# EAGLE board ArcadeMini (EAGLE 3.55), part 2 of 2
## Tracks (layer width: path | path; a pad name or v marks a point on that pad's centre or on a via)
CF_A0  (via drill 0.41 pad 0.81)
  Top 0.254: v79.12,42.81 78.7,42.39 69.79,42.39 67.6,42.39 62.09,47.89 v56.06,47.89 | 35.73,14.24 v39.87,14.24 | v88.45,49.16 99.56,49.16 101.47,47.26 101.47,35.83 103.05,34.24 104.07,34.24 | 44.95,21.23 44.95,22.49 45.59,23.13 v56.06,23.13 | 44.95,21.23 44.95,21.17 | v44.95,19.32 44.95,21.23
  Bottom 0.254: v79.12,42.81 79.88,42.81 81.46,44.4 82.1,44.4 86.86,49.16 v88.45,49.16 | 56.06,48.21 v56.06,47.89 v56.06,23.13 | v39.87,14.24 v44.95,19.32
CF_A1  (via drill 0.41 pad 0.81)
  Top 0.254: v79.12,41.55 78.78,41.89 69.79,41.89 67.15,41.89 62.41,46.62 55.43,46.62 54.48,47.58 54.48,53.61 53.2,54.88 52.24,54.88 | v88.45,47.89 89.08,48.53 99.24,48.53 100.83,46.94 100.83,32.97 101.47,32.34 102.42,32.34 103.05,32.97 104.07,32.97
  Bottom 0.254: v79.12,41.55 79.56,41.55 81.78,43.77 82.42,43.77 86.54,47.89 v88.45,47.89
CF_A2  (via drill 0.41 pad 0.81)
  Top 0.254: v79.12,40.27 78.01,41.39 69.79,41.39 66.7,41.39 62.09,45.99 55.11,45.99 53.83,47.27 53.83,51.06 53.84,51.07 52.57,52.34 52.24,52.34 | v88.45,46.62 88.77,46.62 90.04,47.89 98.93,47.89 100.2,46.62 100.2,32.34 100.83,31.7 104.07,31.7
  Bottom 0.254: v79.12,40.27 79.24,40.27 82.1,43.13 82.73,43.13 86.23,46.62 v88.45,46.62
CF_CD1/  (via drill 0.41 pad 0.81)
  Top 0.254: 69.79,40.89 72.8,40.89 v73.41,40.27 | v94.68,13.92 95.12,14.24 97.34,14.24 99.24,12.34 R16. 99.26,10.75 104.07,10.75
  Bottom 0.254: v73.41,40.27 73.09,39.96 73.09,35.83 74.68,34.24 74.8,27.89 72.89,25.99 72.89,22.81 73.84,21.86 73.84,20.91 76.7,18.05 90.56,18.05 v94.68,13.92
CF_CE/  (via drill 0.41 pad 0.81)
  Top 0.254: v103.89,50.75 103.37,50.75 102.42,51.7 88.02,51.7 86.86,50.55 86.86,42.81 86.44,42.39 83.39,42.39 | 104.01,17.73 104.07,17.73 v107.07,17.73
  Bottom 0.254: v107.07,17.73 107.07,50.12 106.43,50.75 v103.89,50.75
CF_D0  (via drill 0.41 pad 0.81)
  Top 0.254: v93.73,12.65 93.73,11.37 | v73.09,43.45 73.09,44.4 72.34,45.16 72.34,46.44 | 46.22,21.17 46.22,19.95 50.66,15.51 70.35,15.51 73.53,18.69 v73.53,19.95 | 108.13,35.51 v108.02,35.51 104.07,35.51 103.05,35.51 102.1,36.46 102.1,43.13 107.18,48.21 107.18,51.07 102.1,56.15 102.1,60.59 100.83,61.86 100.83,63.08 100.83,63.13
  Bottom 0.254: v73.09,43.45 72.46,43.13 72.46,35.51 74.05,33.92 74.05,28.09 72.26,26.3 72.26,22.49 73.21,21.54 73.21,20.27 v73.53,19.95 76.07,17.41 88.97,17.41 v93.73,12.65 95.32,11.07 104.84,11.07 108.97,15.19 108.97,34.56 v108.02,35.51
CF_D1  (via drill 0.41 pad 0.81)
  Top 0.254: v91.19,12.65 91.19,11.37 | IC2. 71.84,46.62 70.23,46.62 v69.6,47.26 | 47.49,21.17 47.49,19.95 51.3,16.14 68.76,16.14 v71.94,19.32 | 108.13,36.78 v108.02,36.78 104.07,36.78 103.05,36.78 102.73,37.1 102.73,42.81 107.82,47.89 107.82,51.39 102.73,56.47 102.73,61.23 102.1,61.86 102.1,63.08 102.1,63.13
  Bottom 0.254: v69.6,47.26 71.82,45.04 71.82,34.88 73.41,33.29 73.41,28.41 71.62,26.62 71.62,22.18 72.57,21.23 72.57,19.32 | v108.02,36.78 108.65,36.78 109.61,35.83 109.61,14.56 105.48,10.43 93.73,10.43 v91.19,12.65 87.06,16.78 75.43,16.78 72.57,19.32 | v71.94,19.32 72.57,19.32
CF_D2  (via drill 0.41 pad 0.81)
  Top 0.254: v88.65,12.65 88.65,11.37 | 69.79,44.39 70.54,44.39 70.87,44.72 70.87,45.35 70.23,45.99 v69.28,45.99 | 48.76,21.17 48.76,19.95 51.94,16.78 66.86,16.78 70.67,20.59 v71.62,20.59 | 108.13,38.05 v108.02,38.05 104.07,38.05
  Bottom 0.254: v69.28,45.99 71.19,44.09 71.19,34.24 72.78,32.66 72.78,28.73 70.98,26.94 70.98,24.08 | v108.02,38.05 109.29,38.05 110.24,37.1 110.24,13.92 106.11,9.79 91.51,9.79 v88.65,12.65 85.16,16.14 73.53,16.14 70.98,18.69 70.98,20.59 | 70.98,20.59 70.98,24.08 | 70.98,24.08 70.98,24.4 | v71.62,20.59 70.98,20.59
CF_D3  (via drill 0.41 pad 0.81)
  Top 0.254: 86.11,11.37 v86.11,12.65 86.11,13.29 87.7,14.88 98.49,14.88 101.98,11.38 104.07,11.38 | 69.79,43.89 68.84,43.89 68.33,44.4 v68.33,45.04 | 50.03,21.17 50.03,19.95 52.57,17.41 66.22,17.41 v69.4,20.59
  Bottom 0.254: v68.33,45.04 69.28,45.04 70.55,43.77 70.55,33.61 72.26,31.91 72.26,29.48 70.35,27.58 70.35,24.08 | v86.11,12.65 83.25,15.51 73.21,15.51 70.35,18.37 70.35,20.59 | 70.35,20.59 70.35,24.08 | 70.35,24.08 70.35,24.4 | v69.4,20.59 70.35,20.59
CF_D4  (via drill 0.41 pad 0.81)
  Top 0.254: 83.57,11.37 v83.57,12.65 83.57,13.29 85.79,15.51 99.13,15.51 101.98,12.65 104.07,12.65 | 72.34,32.84 72.34,31.58 72.14,31.38 v71.19,31.38 | 51.3,21.17 51.3,19.95 53.2,18.05 64.64,18.05 68.45,21.86 v69.4,21.86
  Bottom 0.254: v83.57,12.65 81.35,14.88 73.84,14.88 | 73.84,14.88 73.21,14.88 | v71.19,31.38 70.35,30.55 70.35,28.53 68.45,26.62 68.45,21.86 | 68.45,21.86 68.45,19.32 72.89,14.88 73.84,14.88 | v69.4,21.86 68.45,21.86
CF_D5  (via drill 0.41 pad 0.81)
  Top 0.254: 81.03,11.37 v81.03,12.65 81.03,13.29 83.89,16.14 99.76,16.14 101.98,13.92 104.07,13.92 | 71.84,32.84 71.84,32.66 v70.23,32.66 | 52.57,21.17 52.57,19.95 53.84,18.69 63.68,18.69 v66.86,21.86
  Bottom 0.254: v81.03,12.65 79.44,14.24 72.57,14.24 67.81,19 67.81,21.86 | 67.81,21.86 67.81,27.26 69.72,29.16 69.72,32.13 v70.23,32.66 | v66.86,21.86 67.81,21.86
CF_D6  (via drill 0.41 pad 0.81)
  Top 0.254: 78.49,11.37 v78.49,12.65 78.49,13.29 81.98,16.78 100.4,16.78 101.98,15.19 104.07,15.19 | 69.79,34.89 69.6,34.89 v69.6,33.92 | IC10. 53.84,19.95 54.48,19.32 62.09,19.32 65.91,23.13 v66.86,23.13
  Bottom 0.254: v78.49,12.65 78.17,12.65 77.22,13.61 72.26,13.61 65.91,19.95 65.91,23.13 | v69.6,33.92 69.08,33.41 69.08,29.8 65.91,26.62 65.91,23.13 | v66.86,23.13 65.91,23.13
CF_D7  (via drill 0.41 pad 0.81)
  Top 0.254: 75.95,11.37 v75.95,12.65 75.95,13.29 80.08,17.41 101.03,17.41 101.98,16.46 104.07,16.46 | v68.33,34.56 68.33,34.88 68.84,35.39 69.79,35.39 | 53.84,30.19 53.92,30.12 63.37,30.12 v65.27,28.21
  Bottom 0.254: v68.33,34.56 68.33,31.27 v65.27,28.21 65.27,19.64 71.94,12.97 75.63,12.97 v75.95,12.65
CF_OE/  (via drill 0.41 pad 0.81)
  Top 0.254: v106.11,49.48 106.11,51.07 103.89,53.29 87.06,53.29 85.59,51.82 85.59,44.09 84.9,43.39 83.39,43.39 | v106.55,16.14 107.18,16.14 107.82,15.51 v107.82,9.79 | v69.72,11.07 66.54,14.24 43.36,14.24 38.6,19 38.6,21.17 | 104.01,20.27 104.07,20.27 v106.23,20.27
  Bottom 0.254: v106.11,49.48 106.43,49.16 106.43,20.59 v106.23,20.27 106.23,16.46 v106.55,16.14 | v107.82,9.79 107.82,8.21 106.86,7.25 105.28,7.25 104.64,7.89 72.89,7.89 v69.72,11.07
CF_RDY  (via drill 0.41 pad 0.81)
  Top 0.254: v75.32,22.81 72.78,22.81 70.87,24.72 68.76,24.72 67.81,25.67 v64,25.67 | 69.79,39.89 66.29,39.89 61.46,44.72 57.33,44.72 56.06,43.45 56.06,38.37 61.14,33.29 v64,33.29 | v95.12,24.08 96.39,24.08 | 96.39,24.08 100.83,24.08 101.47,24.72 104.07,24.72 | 96.39,24.08 R15.
  Bottom 0.254: v64,25.67 v64,33.29 | v75.32,22.81 76.59,24.08 v95.12,24.08
CF_RST/  (via drill 0.41 pad 0.81)
  Top 0.254: v103.26,48.53 103.26,49.28 101.78,50.75 88.45,50.75 87.5,49.8 87.5,42.5 86.89,41.89 83.39,41.89 | 96.39,30.75 v102.1,30.75 103.05,29.8 104.07,29.8
  Bottom 0.254: v103.26,48.53 103.89,48.53 105.16,47.26 105.16,33.81 v102.1,30.75
CF_UCS/  (via drill 0.41 pad 0.81)
  Top 0.254: v74.8,24.08 72.57,24.08 71.3,25.35 69.08,25.35 67.49,26.94 62.09,26.94 59.55,24.4 39.23,24.4 37.33,22.49 37.33,21.17 | 83.39,41.39 87.34,41.39 88.13,42.18 88.13,44.72 89.4,45.99 v98.93,45.99
  Bottom 0.254: v74.8,24.08 75.75,25.03 94.48,25.03 99.56,30.12 99.56,45.35 v98.93,45.99
CF_URST/  (via drill 0.41 pad 0.81)
  Top 0.254: v74.8,25.35 72.89,25.35 72.26,25.99 70.03,25.99 64.95,31.07 58.6,31.07 56.38,33.29 55.24,33.29 | 52.57,30.19 52.57,31.38 54.48,33.29 55.24,33.29 | 83.39,40.89 87.79,40.89 88.77,41.86 88.77,44.4 89.72,45.35 97.97,45.35 v98.61,44.72 | 55.24,33.29 55.23,33.3
  Bottom 0.254: v74.8,25.35 75.11,25.67 94.16,25.67 98.61,30.12 v98.61,44.72
CF_WE/  (via drill 0.41 pad 0.81)
  Top 0.254: v104.21,49.48 104.53,49.48 105.16,50.12 105.16,51.07 103.57,52.66 87.7,52.66 86.23,51.18 86.23,49.8 | 83.39,42.89 85.67,42.89 86.23,43.45 86.23,49.8 | 86.23,49.8 86.23,50.43 | v106.55,8.53 v106.55,14.88 | v70.98,11.07 67.18,14.88 43.68,14.88 39.87,18.69 39.87,21.17 | v101.78,23.45 104.07,23.45
  Bottom 0.254: v104.21,49.48 104.53,49.48 105.8,48.21 105.8,24.08 105.16,23.45 103.37,23.45 | v106.55,14.88 105.91,14.88 103.37,17.41 103.37,23.45 | v70.98,11.07 73.53,8.53 v106.55,8.53 | 103.37,23.45 v101.78,23.45
COL0
  Top 0.254: 69.79,42.89 68.05,42.89 66.54,44.4 66.54,46.62 55.74,57.42 48.12,57.42 43.68,61.86 43.68,63.08 43.68,63.13
COL1
  Top 0.254: 69.79,43.39 68.51,43.39 67.18,44.72 67.18,47.26 56.38,58.05 48.76,58.05 44.95,61.86 44.95,63.08 44.95,63.13
COL2
  Top 0.254: 72.84,46.44 72.84,47.63 66.22,54.24 61.46,54.24 57.02,58.69 49.39,58.69 46.22,61.86 46.22,63.08 46.22,63.13
COL3
  Top 0.254: 73.34,46.44 73.34,48.09 66.54,54.88 62.09,54.88 57.65,59.32 50.03,59.32 47.49,61.86 47.49,63.08 47.49,63.13
COL4
  Top 0.254: 73.84,46.44 73.84,48.54 66.86,55.52 62.73,55.52 58.28,59.96 50.66,59.96 48.76,61.86 48.76,63.08 48.76,63.13
COL5
  Top 0.254: 74.34,46.44 74.34,48.99 67.18,56.15 63.37,56.15 58.92,60.59 51.3,60.59 50.03,61.86 50.03,63.08 50.03,63.13
COL6
  Top 0.254: 74.84,46.44 74.84,49.44 67.49,56.78 64,56.78 59.55,61.23 51.94,61.23 51.3,61.86 51.3,63.08 51.3,63.13
COL7
  Top 0.254: 75.34,46.44 75.34,49.89 67.81,57.42 64.64,57.42 60.19,61.86 60.19,63.08 60.19,63.13
COL8
  Top 0.254: 75.84,46.44 75.84,50.35 68.13,58.05 65.27,58.05 61.46,61.86 61.46,63.08 61.46,63.13
COL9
  Top 0.254: 77.34,46.44 77.34,56.47 75.11,58.69 65.91,58.69 62.73,61.86 62.73,63.08 62.73,63.13
COL10
  Top 0.254: 77.84,46.44 77.84,56.92 75.43,59.32 66.54,59.32 64,61.86 64,63.08 64,63.13
COL11
  Top 0.254: 78.34,46.44 78.34,57.37 75.75,59.96 67.18,59.96 65.27,61.86 65.27,63.08 65.27,63.13
COL12
  Top 0.254: 78.84,46.44 78.84,57.82 76.07,60.59 67.81,60.59 66.54,61.86 66.54,63.08 66.54,63.13
COL13
  Top 0.254: 79.34,46.44 79.34,58.28 76.38,61.23 68.45,61.23 67.81,61.86 67.81,63.08 67.81,63.13
COL14
  Top 0.254: 79.84,46.44 79.84,58.73 76.7,61.86 76.7,63.08 76.7,63.13
COL15
  Top 0.254: 80.34,46.44 80.34,59.5 77.97,61.86 77.97,63.08 77.97,63.13
COL16  (via drill 0.41 pad 0.81)
  Top 0.254: 79.34,32.84 79.34,31.81 v80.4,30.75 | 79.24,63.08 79.24,61.86 86.86,54.24 v96.39,54.24
  Bottom 0.254: v80.4,30.75 82.94,28.21 91.19,28.21 95.64,32.66 95.64,53.49 v96.39,54.24
COL17  (via drill 0.41 pad 0.81)
  Top 0.254: 78.84,32.84 78.84,31.04 v80.4,29.48 | 80.51,63.08 80.51,61.86 86.86,55.52 97.02,55.52 v97.66,54.88
  Bottom 0.254: v80.4,29.48 82.3,27.58 91.83,27.58 96.27,32.02 96.27,52.23 97.66,53.61 v97.66,54.88
COL18  (via drill 0.41 pad 0.81)
  Top 0.254: 81.78,63.08 81.78,61.86 86.86,56.78 93.21,56.78 v94.48,58.05 | 83.39,35.89 84.9,35.89 86.54,34.24 86.54,32.02 v87.5,31.07
  Bottom 0.254: v87.5,31.07 90.04,31.07 93.73,34.88 93.73,56.78 94.48,57.53 v94.48,58.05
COL19  (via drill 0.41 pad 0.81)
  Top 0.254: 83.05,63.08 83.05,61.86 86.86,58.05 93.21,58.05 v94.48,59.32 | 83.39,36.39 85.35,36.39 87.18,34.56 87.18,32.97 v87.81,32.34
  Bottom 0.254: v94.48,59.32 94.48,59.44 93.1,58.05 93.1,35.51 89.92,32.34 v87.81,32.34
COL20  (via drill 0.41 pad 0.81)
  Top 0.254: 84.32,63.08 84.32,61.86 86.86,59.32 v93.21,59.32 | 83.39,36.89 85.8,36.89 88.13,34.56 v88.13,33.61
  Bottom 0.254: v93.21,59.32 93.21,59.44 92.46,58.69 92.46,36.03 90.04,33.61 v88.13,33.61
COL21  (via drill 0.41 pad 0.81)
  Top 0.254: 83.39,37.39 86.46,37.39 v87.7,36.15 | v93.21,61.23 93.21,63.08
  Bottom 0.254: v87.7,36.15 90.56,36.15 91.83,37.42 91.83,59.96 v93.21,61.23
COL22  (via drill 0.41 pad 0.81)
  Top 0.254: 79.84,32.84 79.84,33.85 v79.12,34.56 | 94.48,63.08 94.48,60.91 95.75,59.64 95.75,57.42 v96.39,56.78
  Bottom 0.254: v79.12,34.56 81.46,32.66 81.46,30.63 83.25,28.84 90.56,28.84 95,33.29 95,55.4 v96.39,56.78
COL23  (via drill 0.41 pad 0.81)
  Top 0.254: 80.34,32.84 80.34,34.94 v80.08,35.2 | 95.75,63.13 95.75,63.08 v95.75,61.23
  Bottom 0.254: v80.08,35.2 80.08,34.88 82.1,32.97 82.1,31.27 83.89,29.48 89.92,29.48 94.37,33.92 94.37,56.27 95.75,57.74 v95.75,61.23
COL24  (via drill 0.41 pad 0.81)
  Top 0.254: 78.34,32.84 78.34,30.27 v79.12,29.48 | 97.02,63.08 v97.02,58.69 R17.
  Bottom 0.254: v79.12,29.48 81.67,26.94 92.46,26.94 96.91,31.38 96.91,51.59 98.93,53.61 98.93,56.78 v97.02,58.69
COL25  (via drill 0.41 pad 0.81)
  Top 0.254: 77.84,29.5 77.84,32.84 | v98.29,61.23 98.29,63.08
  Top 0.305: v79.76,26.94 79.76,27.37 77.84,29.3 77.84,29.5
  Bottom 0.254: v79.76,26.94 80.4,26.3 93.1,26.3 97.54,30.75 97.54,50.95 99.56,52.98 99.56,57.42 98.29,58.69 v98.29,61.23
GND  (via drill 0.41 pad 0.81)
  Top 0.254: 71.44,39.39 69.79,39.39 65.84,39.39 64.95,40.27 64.32,40.27 64,40.59 | 73.09,35.83 74.34,34.59 74.34,32.84 74.34,31.53 74.69,31.17 C4. | 77.22,44.72 76.84,45.1 76.84,46.44 76.84,52.52 76.07,53.29 | 105.28,9.16 105.28,9.79 104.96,10.11 104.07,10.11 | 76.84,32.84 76.84,31.52 76.38,31.07 | 83.4,39.89 83.39,39.89 | v80.51,39.89 83.4,39.89 | 101.78,22.18 102.42,22.81 104.07,22.81 105.91,22.81 | C9. 96.72,29.17 96.4,28.86 | 83.4,39.89 88.38,39.89 88.77,40.27 | 106.23,41.23 104.07,41.23 | 104.01,30.43 104.07,30.43 105.8,30.43 | 105.91,29.16 104.07,29.16 | 104.07,27.26 104.07,26.62 104.01,26.62 | 105.91,27.26 104.07,27.26 | 104.07,27.26 104.07,27.89 102.42,27.89 | 104.01,19 104.07,19 105.8,19 | 105.91,24.08 104.07,24.08 | 105.91,21.54 104.07,21.54 | R2. 55.23,35.2 52.27,35.2
  Top 0.406: 73.09,39.32 71.44,39.39 | 73.09,39.32 73.09,35.83 | 77.22,44.72 78.81,44.72 80.51,43.02 v80.51,39.89 79.95,39.32 73.09,39.32
  Top 0.61: 18.91,84.09 22.72,84.09 | 22.72,56.15 22.78,56.15 | 18.91,70.12 22.72,70.12 | 22.72,70.12 22.78,70.12 | 22.78,68.85 22.78,70.07 22.72,70.12 | 22.72,56.15 22.72,54.88 22.78,54.88 | 22.72,84.09 22.78,84.09 | 22.72,84.09 22.78,84.04 22.72,83.99 22.72,82.82 22.78,82.82 22.72,82.77 22.72,81.55 22.78,81.55 | 42.41,69.48 42.41,63.08 | 52.57,63.08 53.79,63.08 53.84,63.13 53.84,63.08 53.89,63.13 53.84,63.19 53.84,69.48 | 58.92,69.48 58.92,63.08 | 69.08,63.08 69.13,63.13 70.35,63.13 | 70.35,63.13 70.35,63.08 | 70.35,69.48 70.35,63.13 | 75.43,69.48 75.43,63.08 | 85.59,63.08 85.64,63.13 86.86,63.13 | 86.86,63.13 86.86,63.08 | 86.86,69.48 86.86,63.13 | 91.94,69.48 91.94,63.08 | 99.56,65.04 99.56,63.08 | 109.61,41.23 106.23,41.23 106.11,41.23 | 109.61,29.16 105.91,29.16 105.8,29.16 | 109.61,19 105.8,19 | 109.61,21.54 105.91,21.54 105.8,21.54 | 109.61,30.43 105.8,30.43 | 109.61,27.26 105.91,27.26 105.8,27.26 | 109.61,24.08 105.91,24.08 105.8,24.08 | 109.61,22.81 105.91,22.81 105.8,22.81 | 93.21,72.1 93.21,69.48 97.66,65.04 99.56,65.04 | 76.7,69.48 76.7,72.1 | 60.19,69.48 60.19,72.1 | 22.72,56.78 22.72,56.15 | 105.28,9.16 105.28,7.89 106.23,6.94 107.18,6.94 109.61,9.36 | 41.14,30.19 41.14,30.12 41.22,30.19 42.41,30.19 43.6,30.19 43.68,30.12 | 43.68,30.12 43.68,30.19 | 43.68,69.48 43.68,72.1 | C4. 76.28,31.17 76.38,31.07 77.02,30.43 77.02,28.84 78.61,27.26 78.61,25.67 80.51,25.67 81.78,26.94 81.78,31.38 82.73,32.34 v82.73,33.61 | C6. 75.43,54.87 75.43,53.93 76.07,53.29 | 86.54,26.95 84.96,28.54 v84.96,30.43 | 86.54,26.95 C7. | 86.54,26.95 86.54,25.35 88.77,23.13 88.77,21.34 | 88.77,21.34 88.65,21.23 | 88.77,21.34 88.77,21.23
  Top 0.61: 51.3,25.67 46.22,25.67 | 46.22,25.67 46.22,30.19 | 46.22,25.67 44.95,25.67 43.68,26.94 43.68,30.12 | 51.3,25.67 51.3,30.19 51.3,32.66 52.27,33.62 52.27,35.2 52.27,38.67 44.95,45.99 44.95,48.53 | 51.3,25.67 v54.48,25.67 57.34,25.67 C10. | 33.52,41.85 33.53,41.86 41.13,41.86 41.14,41.85 42.1,41.85 43.68,40.27 43.68,30.12 | 64,40.59 61.47,43.12 C5. | C8. 101.48,21.87 101.78,22.18 | C9. 101.14,29.17 102.42,27.89 | C17. 96.39,40.6 96.39,39.64 | C16. 96.39,38.68 96.39,39.64 | 96.39,39.64 97.34,39.64 98.61,40.91 98.61,42.81 97.34,44.09 90.99,44.09 89.72,42.81 89.72,41.23 88.77,40.27 | 99.56,65.04 102.73,65.04 103.37,64.41 103.37,63.08
  Top 1.27: 18.91,56.78 18.91,70.12 18.91,84.09 | 39.87,69.48 42.41,69.48 43.68,69.48 53.84,69.48 56.38,69.48 | 72.89,69.48 C13. | 56.38,69.48 58.92,69.48 60.19,69.48 70.35,69.48 72.89,69.48 | 89.4,69.48 C14. | 72.89,69.48 75.43,69.48 76.7,69.48 86.86,69.48 89.4,69.48 | 89.4,69.48 91.94,69.48 93.21,69.48 | 56.38,69.48 C12. | 39.87,69.48 37.96,67.58 37.96,59.32 35.42,56.78 22.72,56.78 18.91,56.78 | 39.87,69.48 C11. | 74.48,15.83 78.61,19.95 78.61,25.67 | 111.94,2.81 135.75,2.81 | 135.75,48.53 114.05,48.53 112.26,46.94 112.26,43.88 109.61,41.23 109.61,30.43 109.61,29.16 109.61,27.26 109.61,24.08 109.61,22.81 109.61,21.54 109.61,19 109.61,9.36 111.94,6.94 111.94,2.81 | 73.21,2.81 73.41,2.81 CON3. 73.41,14.76 74.48,15.83 | 73.21,2.81 111.94,2.81 | 74.48,15.83 74.16,15.51 | 18.3,39.61 18.36,39.61 | 4.3,20.59 C1. 8.12,30.75 11.3,30.75 13.84,33.29 13.84,35.14 18.3,39.61 | 4.3,20.59 C2. 4.32,14.24 4.32,12.96 11.93,5.35 15.74,5.35 | 4.3,20.59 4.63,20.59 | 18.3,39.61 18.33,39.64 18.33,39.37 | 18.33,39.37 18.28,39.32 | 18.91,56.78 18.91,39.96 18.33,39.37 | 15.74,5.35 28.44,5.35 | 15.74,5.35 R14. | 43.78,5.35 43.78,5.41 | 28.44,5.35 C3. | 28.44,5.35 43.78,5.35 | 43.78,5.35 51.3,5.35 | 51.3,5.35 56.22,5.35 CON6. 58.88,2.81 73.21,2.81 | 51.28,8.16 51.3,8.14 51.3,5.35
  Bottom 0.406: v80.51,39.89 82.73,37.67 v82.73,33.61
  Bottom 0.61: v82.73,33.61 82.73,32.02 84.32,30.43 v84.96,30.43
  Bottom 1.27: v54.48,25.67 54.48,21.23 55.43,20.27 57.65,20.27 73.21,5.35 CON3.
N$1
  Top 0.406: 83.57,5.35 R7.
N$2
  Top 0.406: 86.11,5.35 R6.
N$3  (via drill 0.41 pad 0.81)
  Top 0.254: 70.03,28.21 71.51,26.62 v75,26.62 | 70.03,28.21 69.72,28.21 65.91,32.02 61.46,32.02 55.11,38.37 55.11,43.45 57.02,45.35 61.78,45.35 66.74,40.39 69.79,40.39 | 70.03,28.21 R1.
  Bottom 0.254: 93.73,21.23 91.83,23.13 77.97,23.13 76.7,21.86 74.8,21.86 73.84,22.81 73.84,25.67 74.8,26.62 v75,26.62
N$4
  Top 0.406: 88.65,5.35 R5.
N$5
  Top 0.406: 91.19,5.35 R4.
N$6
  Top 0.406: 93.73,5.35 R3.
N$7
  Top 0.254: 92.58,37.42 Q1. | 83.39,38.89 91.1,38.89 92.58,37.42 | 96.4,36.79 93.2,36.79 92.58,37.42
N$8
  Top 0.254: 83.39,39.39 90.1,39.39 92.58,41.86 | 92.58,41.86 92.58,41.89 | 96.4,42.49 93.2,42.49 92.58,41.86
N$9  (via drill 0.41 pad 0.81)
  Top 0.254: 83.39,40.39 82.3,40.39 v81.78,40.91 | v84,32.34 82.73,31.07 82.73,22.06 CON2.
  Bottom 0.254: v81.78,40.91 83.69,39 83.69,32.66 v84,32.34
N$10
  Top 0.254: 83.39,37.89 87.34,37.89 89.08,36.15 89.08,31.07 88.13,30.12 86.86,30.12 85.59,31.38 84.32,31.38 83.37,30.43 83.37,23.97 86.11,21.23
N$11
  Top 0.406: 81.03,5.35 R8.
N$12
  Top 0.406: 78.49,5.35 R9.
N$13
  Top 0.406: 75.95,5.35 R10.
N$14
  Top 0.406: 6.85,52.34 5.58,53.61 3.67,53.61 3.04,52.98 3.04,48.53 5.58,45.99 8.44,45.99 13.76,45.99
N$15
  Top 0.406: 4.31,52.34 4.31,49.16 6.21,47.26 13.76,47.26
N$16
  Top 0.406: 6.85,54.88 8.12,53.61 8.12,50.43 10.03,48.53 13.76,48.53
N$17
  Top 0.406: 4.31,54.88 5.58,56.15 8.75,56.15 9.39,55.52 9.39,51.07 10.66,49.8 13.76,49.8
N$18
  Top 0.406: 6.85,57.42 9.39,57.42 10.66,56.15 10.66,51.7 11.3,51.07 13.76,51.07
N$19  (via drill 0.41 pad 0.81)
  Top 0.406: v11.93,52.34 13.76,52.34
  Bottom 0.406: v11.93,52.34 8.12,56.15 5.58,56.15 4.31,57.42
N$20
  Top 0.406: 6.85,59.96 8.12,58.69 10.66,58.69 11.93,57.42 11.93,54.24 12.57,53.61 13.76,53.61
N$21
  Top 0.406: 4.31,59.96 5.58,61.23 7.49,61.23 8.75,59.96 13.76,59.96
N$22
  Top 0.406: 6.85,62.5 8.12,62.5 9.39,61.23 13.76,61.23
N$23
  Top 0.406: 4.31,62.5 5.58,63.77 8.75,63.77 10.03,62.5 13.76,62.5
N$24
  Top 0.406: 6.85,65.04 9.39,65.04 10.66,63.77 13.76,63.77
N$25
  Top 0.406: 4.31,65.04 5.58,66.31 10.03,66.31 11.3,65.04 13.76,65.04
N$26
  Top 0.406: 6.85,67.58 10.66,67.58 11.93,66.31 13.76,66.31
N$27
  Top 0.406: 4.31,67.58 5.58,68.85 11.3,68.85 12.57,67.58 13.76,67.58
N$28
  Top 0.406: CON5. 9.39,80.28 13.76,80.28
N$29
  Top 0.406: 6.85,75.2 10.66,79.01 13.76,79.01
N$30
  Top 0.406: 4.31,72.66 5.58,73.93 7.49,73.93 11.3,77.74 13.76,77.74
N$31
  Top 0.406: 6.85,72.66 8.12,72.66 11.93,76.47 13.76,76.47
N$32
  Top 0.406: 4.31,70.12 5.58,71.39 8.75,71.39 12.57,75.2 13.76,75.2
N$33
  Top 0.406: 6.85,70.12 9.39,70.12 13.2,73.93 13.76,73.93
N$34
  Top 0.406: 57.65,80.28 57.65,79.01 56.38,77.74 47.49,77.74 44.95,75.2 44.95,72.1
N$35  (via drill 0.41 pad 0.81)
  Top 0.406: 46.22,72.1 v46.22,73.93
  Bottom 0.406: v46.22,73.93 48.76,76.47 55.11,76.47 56.38,77.74 56.38,81.55 57.65,82.82
N$36
  Top 0.406: 60.19,80.28 60.19,79.01 57.65,76.47 49.39,76.47 47.49,74.56 47.49,72.1
N$37  (via drill 0.41 pad 0.81)
  Top 0.406: 48.76,72.1 v48.76,73.93
  Bottom 0.406: v48.76,73.93 50.03,75.2 56.38,75.2 58.92,77.74 58.92,81.55 60.19,82.82
N$38
  Top 0.406: 62.73,80.28 62.73,79.01 58.92,75.2 50.66,75.2 50.03,74.56 50.03,72.1
N$39  (via drill 0.41 pad 0.81)
  Top 0.406: 51.3,72.1 v51.3,73.93
  Bottom 0.406: v51.3,73.93 57.65,73.93 61.46,77.74 61.46,81.55 62.73,82.82
N$40
  Top 0.406: 65.27,80.28 65.27,79.64 59.55,73.93 53.2,73.93 52.57,73.3 52.57,72.1
N$41  (via drill 0.41 pad 0.81)
  Top 0.406: 61.46,72.1 v61.46,73.93
  Bottom 0.406: v61.46,73.93 61.46,75.83 64,78.38 64,81.55 65.27,82.82
N$42
  Top 0.406: 67.81,80.28 67.81,79.64 62.73,74.56 62.73,72.1
N$43  (via drill 0.41 pad 0.81)
  Top 0.406: 64,72.1 v64,73.93
  Bottom 0.406: 67.81,82.82 66.54,81.55 66.54,77.74 64,75.2 v64,73.93
N$44
  Top 0.406: 70.35,80.28 70.35,79.64 65.27,74.56 65.27,72.1
N$45  (via drill 0.41 pad 0.81)
  Top 0.406: 66.54,72.1 v66.54,73.93
  Bottom 0.406: v66.54,73.93 66.54,74.56 69.08,77.11 69.08,81.55 70.35,82.82
N$46
  Top 0.406: 72.89,80.28 72.89,79.64 67.81,74.56 67.81,72.1
N$47
  Top 0.406: 72.89,82.82 74.16,81.55 74.16,79.01 69.08,73.93 69.08,72.1
N$48
  Top 0.406: CON4. 91.94,79.01 96.39,79.01 99.56,75.83 99.56,72.1
N$49
  Top 0.406: 88.13,80.28 90.67,77.74 95.75,77.74 98.29,75.2 98.29,72.1 98.29,72.02
N$50
  Top 0.406: 85.59,82.82 86.86,81.55 86.86,79.01 89.4,76.47 95.12,76.47 97.02,74.56 97.02,72.1 97.02,72.02
N$51
  Top 0.406: 85.59,80.28 85.59,78.38 88.77,75.2 94.48,75.2 95.75,73.93 95.75,72.1
N$52
  Top 0.406: 83.05,82.82 84.32,81.55 84.32,77.74 88.13,73.93 93.85,73.93 94.48,73.3 94.48,72.1
N$53
  Top 0.406: 83.05,80.28 83.05,77.74 85.59,73.93 85.59,72.1
N$54
  Top 0.406: 80.51,82.82 81.78,81.55 81.78,77.74 84.32,73.93 84.32,72.1
N$55
  Top 0.406: 80.51,80.28 80.51,77.74 83.05,73.93 83.05,72.1
N$56
  Top 0.406: 77.97,82.82 79.24,81.55 79.24,77.74 81.78,73.93 81.78,72.1
N$57
  Top 0.406: 77.97,80.28 77.97,77.74 80.51,73.93 80.51,72.1
N$58
  Top 0.406: 75.43,82.82 76.7,81.55 76.7,77.74 79.24,73.93 79.24,72.1
N$59
  Top 0.406: 75.43,80.28 75.43,77.74 77.97,73.93 77.97,72.1
N$60
  Top 0.254: 39.58,39.64 Q2. 39.87,35.54 39.87,30.19 39.87,30.12 | 39.58,39.64 38.27,39.64 | 39.58,39.64 39.55,39.61 40.8,39.61 41.14,39.96 C19.
N$61
  Top 0.254: 35.08,39.64 35.08,35.83 35.08,34.91 38.6,31.38 38.6,30.19 38.6,30.12 | 35.08,39.64 R11. | C18. 33.52,39.96 33.84,39.64 35.08,39.64
N$62
  Top 0.254: 46.22,35.5 46.22,35.51 49.06,35.51 C15.
  Top 0.61: 50.03,30.19 50.03,32.66 49.06,33.62 C15.
N$63
  Top 1.27: D2. 13.2,20.59 IC1. 28.44,20.59
  Top 6.452: 19.55,24.4 28.44,24.4 28.44,20.59 28.44,16.78 19.55,16.78
N$64  (via drill 0.41 pad 0.81)
  Top 0.254: v47.49,28.21 47.49,30.19
  Bottom 0.254: 48.76,10.14 48.76,10.11 | 48.78,10.16 48.76,10.14 | v47.49,28.21 48.76,28.21 49.39,27.58 49.39,26.62 48.76,25.99 48.76,10.14
N$65  (via drill 0.41 pad 0.81)
  Top 0.254: v48.12,26.94 48.76,27.58 48.76,30.19 48.76,31.38 46.52,33.62 R12.
  Bottom 0.254: v48.12,26.94 48.12,11.7 47.17,10.75 47.17,9.48 48.44,8.21 48.76,8.21 48.76,8.18 48.78,8.16
N$66
  Top 1.27: D4. 40.82,10.11 43.36,12.65 49.71,12.65 51.3,11.07 51.3,10.18 51.28,10.16
N$67
  Top 0.406: 95.43,20.91 96.07,21.54 96.07,19.95
N$68
  Top 0.406: 98.29,5.99 98.93,6.62 98.93,4.71
N$69
  Top 0.406: 55.11,80.28 55.74,80.91 55.74,79.01
N$70
  Top 0.406: 6.21,49.8 6.85,50.43 6.85,48.53
N$71
  Top 0.254: 44.62,52.34 44.95,52.34 46.22,51.07 46.22,47.89 47.49,46.62 49.39,46.62 50.03,47.26 50.03,48.53 50.03,52.01 R19.
N$72
  Top 0.254: 47.49,54.88 R18. | 47.49,54.88 44.62,54.88 | CON7. 47.49,54.88
N$73
  Top 0.406: 34.79,49.8 35.42,50.43 35.42,48.53
N$74  (via drill 0.41 pad 0.81)
  Top 0.254: 102.1,72.1 102.1,70.75 99.56,68.22 v96.39,68.22 | v39.87,67.26 39.87,57.74 32.88,50.75 32.88,48.21 35.11,45.99 37.96,45.99 39.87,47.89 39.87,48.53
  Bottom 0.254: v96.39,68.22 96.07,67.9 41.77,67.9 41.46,68.22 40.82,68.22 v39.87,67.26
N$75  (via drill 0.41 pad 0.81)
  Top 0.254: 103.37,72.1 103.37,70.75 99.56,66.95 v97.66,66.95 | v41.14,67.26 40.51,66.63 40.51,57.42 33.52,50.43 33.52,48.53 35.42,46.62 37.65,46.62 38.6,47.58 38.6,49.16 39.23,49.8 40.51,49.8 41.77,48.53 42.41,48.53
  Bottom 0.254: v97.66,66.95 96.07,66.95 95.75,67.26 v41.14,67.26
PWR1
  Top 1.27: CON1. 10.58,34.56
PWR2
  Top 1.27: 10.66,39.64 D1. 5.58,39.64
ROW0  (via drill 0.41 pad 0.81)
  Top 0.254: 22.72,45.99 22.78,45.99 v24.63,45.99 | v57.02,39.64 57.02,38.37 60.82,34.56 65.27,34.56 70.35,29.48 72.26,29.48 73.34,30.56 73.34,32.84
  Bottom 0.254: v24.63,45.99 25.27,45.99 32.25,52.98 52.57,52.98 57.02,48.53 v57.02,39.64
ROW1  (via drill 0.41 pad 0.81)
  Top 0.254: 22.78,47.26 v24.63,47.26 | 72.84,32.84 72.84,31.33 71.62,30.12 70.98,30.12 65.91,35.2 61.14,35.2 57.97,38.37 v57.97,38.69
  Bottom 0.254: v24.63,47.26 25.27,47.26 31.61,53.61 53.2,53.61 57.97,48.85 v57.97,38.69
ROW2  (via drill 0.41 pad 0.81)
  Top 0.254: 69.79,35.89 61.4,35.89 58.92,38.37 v58.92,39.64 | 22.78,48.53 v24.63,48.53
  Bottom 0.254: v58.92,39.64 58.92,49.16 53.84,54.24 30.98,54.24 25.27,48.53 v24.63,48.53
ROW3  (via drill 0.41 pad 0.81)
  Top 0.254: 69.79,36.39 61.85,36.39 59.87,38.37 v59.87,38.69 | 22.78,49.8 v24.63,49.8
  Bottom 0.254: v59.87,38.69 59.87,49.48 54.48,54.88 30.34,54.88 25.27,49.8 v24.63,49.8
ROW4  (via drill 0.41 pad 0.81)
  Top 0.254: 69.79,36.89 62.3,36.89 60.82,38.37 v60.82,39.64 | 22.78,51.07 v24.63,51.07
  Bottom 0.254: v60.82,39.64 60.82,49.8 55.11,55.52 29.71,55.52 25.27,51.07 v24.63,51.07
ROW5  (via drill 0.41 pad 0.81)
  Top 0.254: 22.78,52.34 v24.63,52.34 | 69.79,37.39 62.76,37.39 61.78,38.37 v61.78,38.69
  Bottom 0.254: v24.63,52.34 25.27,52.34 29.07,56.15 55.74,56.15 61.78,50.12 v61.78,38.69
ROW6  (via drill 0.41 pad 0.81)
  Top 0.254: 69.79,37.89 63.53,37.89 v63.05,38.37 | 22.78,53.61 v24.63,53.61
  Bottom 0.254: v24.63,53.61 25.27,53.61 28.44,56.78 56.38,56.78 63.05,50.12 v63.05,38.37
ROW7  (via drill 0.41 pad 0.81)
  Top 0.254: 22.72,59.96 22.78,59.96 27.17,59.96 v28.44,58.69 | 69.79,38.39 64.62,38.39 v64.32,38.69
  Bottom 0.254: v64.32,38.69 64.32,50.12 57.02,57.42 29.71,57.42 v28.44,58.69
ROW8  (via drill 0.41 pad 0.81)
  Top 0.254: 22.78,61.23 v25.27,61.23 | 80.84,46.44 80.84,44.91 v80.4,44.72
  Bottom 0.254: v25.27,61.23 25.9,61.23 27.8,63.13 62.73,63.13 63.25,62.5 80.4,45.35 v80.4,44.72
ROW9  (via drill 0.41 pad 0.81)
  Top 0.254: 22.78,62.5 v25.27,62.5 | 81.34,46.44 81.85,46.44 v82.3,45.99
  Bottom 0.254: 80.4,46.62 63.88,63.13 63.37,63.77 27.17,63.77 25.9,62.5 v25.27,62.5 | 80.4,46.62 80.58,46.44 | v82.3,45.99 81.03,45.99 80.4,46.62
ROW10  (via drill 0.41 pad 0.81)
  Top 0.254: 22.78,63.77 v25.27,63.77 | 83.39,44.39 83.25,44.39 83.25,53.41 v83.05,53.61
  Bottom 0.254: v25.27,63.77 25.9,64.41 72.26,64.41 v83.05,53.61
ROW11  (via drill 0.41 pad 0.81)
  Top 0.254: 22.78,65.04 v25.27,65.04 | 83.39,43.89 84.21,43.89 84.64,44.32 84.64,53.29 v83.05,54.88
  Bottom 0.254: v25.27,65.04 72.89,65.04 v83.05,54.88
ROW12  (via drill 0.41 pad 0.81)
  Top 0.254: v24.63,66.31 22.78,66.31 | 80.84,32.84 80.84,35.71 v79.12,37.42
  Bottom 0.254: v24.63,66.31 23.36,65.04 23.36,61.23 24.63,59.96 25.9,59.96 28.44,62.5 62.09,62.5 77.22,47.26 77.22,43.13 77.54,42.81 77.54,39.32 77.86,39 77.86,37.73 78.17,37.42 v79.12,37.42
ROW13  (via drill 0.41 pad 0.81)
  Top 0.254: v24.63,67.58 22.78,67.58 | 81.34,32.84 81.34,36.16 v81.67,36.46
  Bottom 0.254: v24.63,67.58 23.99,67.58 22.72,66.31 22.72,60.59 23.99,59.32 26.54,59.32 29.07,61.86 61.46,61.86 76.59,46.62 76.59,42.81 76.9,42.5 76.9,39 77.22,38.69 77.22,36.78 77.54,36.46 v81.67,36.46
ROW14  (via drill 0.41 pad 0.81)
  Top 0.254: v27.17,66.95 27.17,70.75 23.99,73.93 22.78,73.93 | 83.39,34.89 84,34.88 84.64,34.27 v84.64,33.61
  Bottom 0.254: v27.17,66.95 28.44,65.67 73.84,65.67 90.56,48.96 90.56,38.69 89.6,37.73 85.91,37.73 84.64,36.46 v84.64,33.61
ROW15  (via drill 0.41 pad 0.81)
  Top 0.254: v28.44,67.58 28.44,71.39 24.63,75.2 22.78,75.2 | 83.39,35.39 84.44,35.39 85.59,34.24 v85.59,32.66
  Bottom 0.254: v28.44,67.58 29.71,66.31 74.48,66.31 91.19,49.6 91.19,38.37 89.92,37.1 86.43,37.1 85.59,36.26 v85.59,32.66
ROW16  (via drill 0.41 pad 0.81)
  Top 0.254: v29.71,60.59 29.71,72.02 25.27,76.47 22.78,76.47 | 76.34,32.84 76.34,35.26 v76.59,35.51
  Bottom 0.254: v76.59,35.51 76.59,38.05 76.27,38.37 76.27,42.18 75.95,42.5 75.95,45.99 60.82,61.23 30.34,61.23 v29.71,60.59
ROW17  (via drill 0.41 pad 0.81)
  Top 0.254: v30.98,59.96 30.98,72.66 25.9,77.74 22.78,77.74 | 75.84,32.84 75.84,36.03 75.95,37.42 v75.63,37.73
  Bottom 0.254: v75.63,37.73 75.63,41.55 75.32,41.86 75.32,45.35 60.19,60.59 31.61,60.59 v30.98,59.96
ROW18  (via drill 0.41 pad 0.81)
  Top 0.254: v32.25,59.32 32.25,73.3 26.54,79.01 22.78,79.01 | 75.34,32.84 75.34,35.81 v75,36.78
  Bottom 0.254: v75,36.78 74.68,37.1 74.68,38.05 75,38.37 75,41.23 74.68,41.55 74.68,44.72 59.55,59.96 32.88,59.96 v32.25,59.32
ROW19  (via drill 0.41 pad 0.81)
  Top 0.254: v33.52,58.69 33.52,73.93 27.17,80.28 22.78,80.28 | 74.84,32.84 74.84,35.36 v74.05,36.15
  Bottom 0.254: v74.05,36.15 74.05,38.37 74.36,38.69 74.36,40.91 74.05,41.23 74.05,44.09 58.92,59.32 34.16,59.32 v33.52,58.69
S$1
  Top 0.254: 116.27,19.32 116.27,44.72
S$2
  Top 0.254: 123.89,19.32 123.89,44.72
S$4
  Top 0.406: 130.88,12.97 134.05,12.97 | 130.88,12.97 127.7,12.97 127.7,14.24 128.97,15.51 129.61,15.51 130.88,14.88 130.88,12.97 | 130.88,12.97 134.05,15.51
S$5
  Top 0.406: 134.05,19.32 134.05,18.05 132.78,16.78 128.97,16.78 127.7,18.05 127.7,19.32
S$6
  Top 0.406: 123.58,17.41 123.26,17.41
S$7
  Top 0.406: 131.51,11.07 134.05,11.7 | 131.51,11.07 127.7,9.79 131.51,8.53 | 131.51,8.53 131.51,11.07 | 131.51,8.53 134.05,7.89
S$8
  Top 0.406: 131.51,23.77 134.05,24.4 | 131.51,23.77 127.7,22.49 131.51,21.23 | 131.51,21.23 131.51,23.77 | 131.51,21.23 134.05,20.59
S$10
  Top 0.254: 113.73,10.43 113.73,7.89 115,7.89 | 113.73,10.43 113.73,15.51 | 113.73,15.51 113.73,17.41 114.37,18.05 124.53,18.05 124.53,16.78 | 115,9.16 115,6.62 125.8,6.62 125.8,7.89 | 115,10.43 115,9.16 | 115,10.43 115,12.97 | 115,12.97 115,14.24 | 115,15.51 115,14.24 | 115,15.51 115,16.14 115.64,16.78 124.53,16.78 | 124.53,16.78 125.8,16.78 125.8,15.51 | 125.8,7.89 125.8,15.51 | 115,9.16 118.18,9.16 118.18,14.24 115,14.24 | 113.73,10.43 115,10.43 | 113.73,15.51 115,15.51 | 115,12.97 114.37,12.97 114.37,14.24 115,14.24 | 125.8,7.89 119.45,7.89 119.45,15.51 125.8,15.51
S$11
  Top 0.61: 124.53,9.16 124.53,14.24
S$12
  Top 0.406: 124.85,16.14 124.53,16.14
S$13
  Top 0.254: 115.64,11.7 115.64,12.97 117.54,12.97 117.54,11.7 115.64,11.7
S$14
  Top 0.61: 120.72,9.16 120.72,14.24
S$15
  Top 0.61: 121.99,9.16 121.99,14.24
S$16
  Top 0.61: 123.26,9.16 123.26,14.24
S$17
  Top 0.406: 124.85,7.25 124.53,7.25
S$18
  Top 0.406: 127.7,25.67 134.05,25.67 134.05,26.94 132.78,28.21 128.97,28.21 127.7,26.94 127.7,25.67
S$19
  Top 0.406: 130.88,29.48 127.7,29.48 127.7,32.02 | 130.88,29.48 134.05,29.48 134.05,32.02 | 130.88,29.48 130.88,31.38
S$20
  Top 0.254: 132.15,33.29 134.05,33.29 | 132.15,33.29 131.51,33.29 | 132.15,33.29 131.51,33.92 131.51,34.56 132.15,34.56 | 132.15,34.56 134.05,34.56 | 132.15,34.56 131.51,35.2 131.51,35.83 134.05,35.83
S$21
  Top 0.254: 131.51,37.1 133.42,37.1 134.05,37.73
S$22
  Top 0.254: 129.61,37.1 130.24,37.1
S$23
  Top 0.254: 134.05,40.27 131.51,40.27 131.51,39.64 132.15,39 | 132.15,39 131.51,39 | 132.15,39 134.05,39
S$24
  Top 0.254: 131.51,41.55 133.42,41.55 134.05,42.18
S$25
  Top 0.254: 129.61,41.55 130.24,41.55
VCC  (via drill 0.41 pad 0.81, 1.02 pad 1.68)
  Top 0.254: 77.22,43.77 76.34,44.65 76.34,46.44 76.34,51.43 75.43,52.34 | 77.34,32.84 77.34,34.88 77.97,35.51 | 102.42,20.91 102.42,18.37 104.07,18.37 | 102.42,20.91 102.42,21.54 103.05,22.18 104.07,22.18 | v102.1,33.29 102.42,33.61 104.07,33.61 | 75.43,29.29 74.35,29.29 73.84,29.8 73.84,32.84 73.84,34.13 72.46,35.51 72.46,37.42 70.98,38.89 69.79,38.89 65.39,38.89 64.64,39.64 63.37,39.64 | 80.4,38.37 81.15,38.37 81.17,38.39 83.39,38.39 87.79,38.39 89.72,36.46 89.72,30.12 | 102.62,25.99 CF1. 104.07,25.35 104.01,25.35 | 102.42,20.91 104.07,20.91 | v43.68,23.13 43.68,21.17 | 99.24,8.86 99.23,8.84 96.27,8.84
  Top 0.406: v78.17,43.77 77.22,43.77 | v80.4,37.42 80.4,38.37 78.61,38.37 77.97,37.73 77.97,35.51 v78.17,35.51
  Top 0.61: 56.38,72.33 57.34,72.33 v57.65,72.02 58.92,72.02 IC4. | 89.4,72.33 90.37,72.33 v90.67,72.02 91.94,72.02 IC6. | 72.89,72.33 73.86,72.33 v74.16,72.02 75.43,72.02 IC5. | IC3. 42.41,72.02 v41.14,72.02 40.82,72.33 39.87,72.33 39.86,72.34 | 102.62,25.99 v101.78,25.99 99.56,25.99 | 99.56,18.37 92.89,18.37 91.19,20.07 91.19,21.11 | 91.19,21.23 91.19,21.11 | 91.19,21.11 91.31,21.23 91.31,25.99 | 75.43,28.21 v76.7,26.94 v76.7,20.59 74.8,20.59 73.53,21.86 71.62,21.86 69.72,23.77 68.13,23.77 67.49,24.4 v62.73,24.4 | 75.43,28.21 75.43,29.29 | 75.43,28.21 72.13,28.21 | 73.54,54.88 73.54,54.23 75.43,52.34 | 91.31,25.99 90.35,26.94 89.72,26.94 | 89.72,26.94 88.44,26.94 88.13,26.94 | v44.95,32.02 44.95,30.19 | v53.2,27.58 57.64,27.58 57.65,27.56 v59.55,27.58 | R20. R21. 39.87,52.34 37.33,49.8 37.33,48.53 | 58.92,41.24 61.77,41.24 63.37,39.64 | 99.56,18.37 99.56,18.67 | 99.56,18.37 102.42,18.37 | 99.56,25.99 99.56,25.98 | 96.39,25.99 99.56,25.99 | 96.39,25.99 96.39,25.98 | 91.31,25.99 96.39,25.99 | 89.72,26.94 89.72,30.12 | 100.18,58.69 100.18,58.68 v100.2,60.59
  Top 1.27: 96.27,5.35 96.27,8.84 v96.27,12.65 | 35.43,10.11 v32.25,10.11 28.45,10.11 28.44,10.12 28.43,10.11 | 28.43,10.11 28.44,10.11 | 23.36,10.11 28.43,10.11
  Bottom 0.254: v43.68,23.13 44.95,24.4 v44.95,32.02
  Bottom 0.406: v78.17,43.77 78.17,39.64 v80.4,37.42
  Bottom 0.61: 41.14,69.48 v41.14,72.02 | 74.16,69.48 v74.16,72.02 | v90.67,72.02 90.67,69.48 97.02,69.48 100.2,66.31 v100.2,60.59 | 57.65,69.48 v57.65,72.02 | v102.1,33.29 100.83,32.02 100.83,26.94 v101.78,25.99 | v76.7,26.94 76.7,29.16 78.17,30.63 v78.17,35.51 | v53.2,27.58 48.76,32.02 v44.95,32.02 37.33,39.64 37.33,48.53 | v62.73,24.4 v59.55,27.58
  Bottom 1.27: 90.67,69.48 74.16,69.48 57.65,69.48 41.14,69.48 23.36,69.48 20.18,65.99 18.91,64.72 18.91,23.45 v32.25,10.11 40.82,1.54 57.33,1.54 58.6,2.81 93.73,2.81 96.27,5.35 | v96.27,12.65 96.27,14.99 91.94,19.32 91.19,19.32 | v76.7,20.59 77.97,19.32 91.19,19.32 | 91.19,19.32 91.19,21.23
VIN
  Top 1.27: 8.75,26.94 8.77,26.94 13.2,26.94 | 13.2,23.13 13.2,26.94 | 18.36,34.56 18.36,32.1 13.2,26.94
VOUT
  Top 0.254: D3. 21.46,12.02 31.63,12.02 R13.
  Top 1.27: 8.75,14.24 8.77,14.24 13.2,14.24 | 13.2,14.24 13.2,12.65 15.74,10.11 | 15.74,10.11 D3. | 15.74,10.11 15.74,8.83 | 13.2,14.24 13.2,18.05

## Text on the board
Top: TOP
Bottom: BOTTOM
